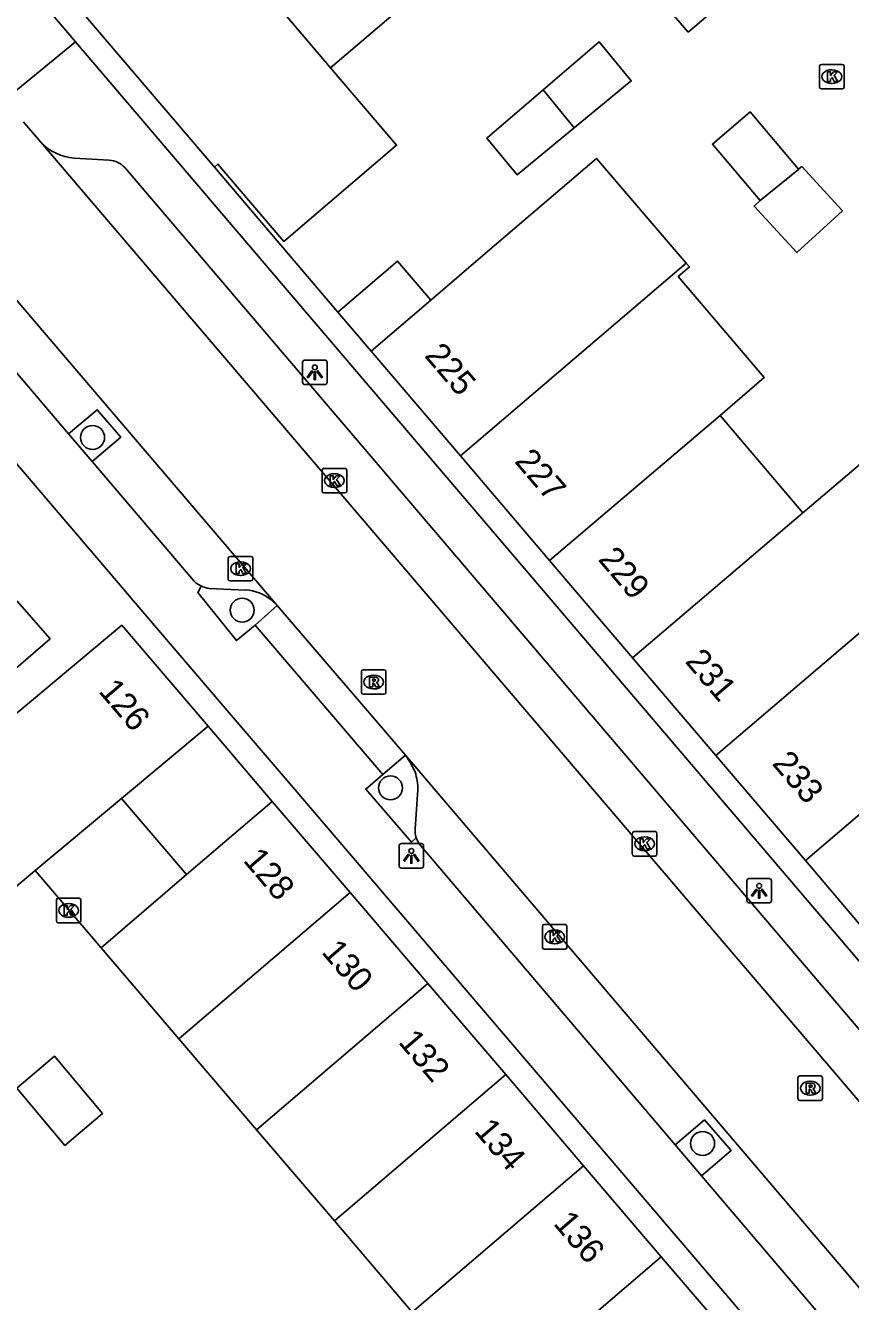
# Model space of a CAD drawing. Extents: x 160379 to 161131, y 383940 to 384849.
# Drawn here: x 160748.4 to 160782, y 384618.3 to 384670.3 of the extents above; entities that cross this region are included whole.
import ezdxf

# ---------------------------------------------------------------- set-up
doc = ezdxf.new("R2010")
doc.units = 0
for name, color, linetype in [('IMGEO_Boom', 7, 'Continuous'), ('IMGEO_Kolk', 7, 'Continuous'), ('IMGEO_Lichtpunt', 7, 'Continuous'), ('IMGEO_Muur', 7, 'Continuous'), ('IMGEO_Pand', 7, 'Continuous'), ('IMGEO_Pand_nummerreeks', 7, 'Continuous'), ('IMGEO_Pand_overbouw', 7, 'Continuous'), ('IMGEO_Parkeervlak_open', 7, 'Continuous'), ('IMGEO_Rijbaan_lokaal_open', 7, 'Continuous'), ('IMGEO_Rioolput', 7, 'Continuous'), ('IMGEO_Voetpad_open', 7, 'Continuous')]:
    doc.layers.add(name, color=color, linetype=linetype)

msp = doc.modelspace()

# ---------------------------------------------------------------- linework, layer by layer
at = {"layer": 'IMGEO_Boom'}
for centre in [(160751.133, 384653.538), (160757.232, 384646.499), (160763.277, 384639.257), (160775.998, 384624.766)]:
    msp.add_circle(centre, 0.489, dxfattribs=at)
at = {"layer": 'IMGEO_Kolk'}
for p, q in [((160780.765, 384667.817), (160780.765, 384668.669)), ((160780.84, 384668.743), (160781.692, 384668.743)), ((160781.766, 384668.669), (160781.766, 384667.817)), ((160781.253, 384668.523), (160781.278, 384668.523)), ((160781.692, 384667.743), (160780.84, 384667.743)), ((160781.276, 384667.963), (160781.251, 384667.963)), ((160760.49, 384651.353), (160760.49, 384652.205)), ((160760.565, 384652.279), (160761.417, 384652.279)), ((160760.978, 384652.059), (160761.003, 384652.059)), ((160761.491, 384652.205), (160761.491, 384651.353)), ((160761.001, 384651.499), (160760.976, 384651.499)), ((160761.417, 384651.279), (160760.565, 384651.279)), ((160756.663, 384647.764), (160756.663, 384648.616)), ((160756.738, 384648.69), (160757.59, 384648.69)), ((160757.151, 384648.47), (160757.176, 384648.47)), ((160757.664, 384648.616), (160757.664, 384647.764)), ((160757.174, 384647.91), (160757.149, 384647.91)), ((160757.59, 384647.69), (160756.738, 384647.69)), ((160773.209, 384637.478), (160774.061, 384637.478)), ((160773.134, 384636.552), (160773.134, 384637.404)), ((160773.622, 384637.258), (160773.647, 384637.258)), ((160774.135, 384637.404), (160774.135, 384636.552)), ((160774.061, 384636.478), (160773.209, 384636.478)), ((160773.645, 384636.698), (160773.62, 384636.698)), ((160749.658, 384633.837), (160749.658, 384634.689)), ((160749.733, 384634.763), (160750.585, 384634.763)), ((160750.146, 384634.543), (160750.171, 384634.543)), ((160750.659, 384634.689), (160750.659, 384633.837)), ((160750.169, 384633.983), (160750.144, 384633.983)), ((160750.585, 384633.763), (160749.733, 384633.763)), ((160769.469, 384632.758), (160769.469, 384633.61)), ((160769.544, 384633.684), (160770.396, 384633.684)), ((160769.957, 384633.464), (160769.982, 384633.464)), ((160770.47, 384633.61), (160770.47, 384632.758)), ((160769.98, 384632.904), (160769.955, 384632.904)), ((160770.396, 384632.684), (160769.544, 384632.684))]:
    msp.add_line(p, q, dxfattribs=at)
for points in [[(160780.765, 384667.817), (160780.765, 384668.669)], [(160780.84, 384668.743), (160781.692, 384668.743)], [(160781.766, 384668.669), (160781.766, 384667.817)], [(160781.086, 384668.443), (160781.209, 384668.443), (160781.209, 384668.292), (160781.339, 384668.443), (160781.503, 384668.443), (160781.357, 384668.292), (160781.51, 384668.043), (160781.358, 384668.043), (160781.273, 384668.207), (160781.209, 384668.14), (160781.209, 384668.043), (160781.086, 384668.043), (160781.086, 384668.443)], [(160781.692, 384667.743), (160780.84, 384667.743)], [(160760.49, 384651.353), (160760.49, 384652.205)], [(160760.565, 384652.279), (160761.417, 384652.279)], [(160760.811, 384651.979), (160760.934, 384651.979), (160760.934, 384651.828), (160761.064, 384651.979), (160761.228, 384651.979), (160761.082, 384651.828), (160761.235, 384651.579), (160761.083, 384651.579), (160760.998, 384651.743), (160760.934, 384651.676), (160760.934, 384651.579), (160760.811, 384651.579), (160760.811, 384651.979)], [(160761.491, 384652.205), (160761.491, 384651.353)], [(160761.417, 384651.279), (160760.565, 384651.279)], [(160756.663, 384647.764), (160756.663, 384648.616)], [(160756.738, 384648.69), (160757.59, 384648.69)], [(160756.984, 384648.39), (160757.107, 384648.39), (160757.107, 384648.239), (160757.237, 384648.39), (160757.401, 384648.39), (160757.255, 384648.239), (160757.408, 384647.99), (160757.256, 384647.99), (160757.171, 384648.154), (160757.107, 384648.087), (160757.107, 384647.99), (160756.984, 384647.99), (160756.984, 384648.39)], [(160757.664, 384648.616), (160757.664, 384647.764)], [(160757.59, 384647.69), (160756.738, 384647.69)], [(160773.209, 384637.478), (160774.061, 384637.478)], [(160773.134, 384636.552), (160773.134, 384637.404)], [(160773.455, 384637.178), (160773.578, 384637.178), (160773.578, 384637.027), (160773.708, 384637.178), (160773.872, 384637.178), (160773.726, 384637.027), (160773.879, 384636.778), (160773.727, 384636.778), (160773.642, 384636.942), (160773.578, 384636.875), (160773.578, 384636.778), (160773.455, 384636.778), (160773.455, 384637.178)], [(160774.135, 384637.404), (160774.135, 384636.552)], [(160774.061, 384636.478), (160773.209, 384636.478)], [(160749.658, 384633.837), (160749.658, 384634.689)], [(160749.733, 384634.763), (160750.585, 384634.763)], [(160749.979, 384634.463), (160750.102, 384634.463), (160750.102, 384634.312), (160750.232, 384634.463), (160750.396, 384634.463), (160750.25, 384634.312), (160750.403, 384634.063), (160750.251, 384634.063), (160750.166, 384634.227), (160750.102, 384634.16), (160750.102, 384634.063), (160749.979, 384634.063), (160749.979, 384634.463)], [(160750.659, 384634.689), (160750.659, 384633.837)], [(160750.585, 384633.763), (160749.733, 384633.763)], [(160769.469, 384632.758), (160769.469, 384633.61)], [(160769.544, 384633.684), (160770.396, 384633.684)], [(160769.79, 384633.384), (160769.913, 384633.384), (160769.913, 384633.233), (160770.043, 384633.384), (160770.207, 384633.384), (160770.061, 384633.233), (160770.214, 384632.984), (160770.062, 384632.984), (160769.977, 384633.148), (160769.913, 384633.081), (160769.913, 384632.984), (160769.79, 384632.984), (160769.79, 384633.384)], [(160770.47, 384633.61), (160770.47, 384632.758)], [(160770.396, 384632.684), (160769.544, 384632.684)]]:
    msp.add_lwpolyline(points, dxfattribs=at)
for centre, start, end in [((160780.842, 384668.667), 91.552, 178.448), ((160780.842, 384668.667), 91.552, 178.448), ((160781.69, 384668.667), 1.552, 88.448), ((160781.69, 384668.667), 1.552, 88.448), ((160780.842, 384667.819), 181.552, 268.448), ((160780.842, 384667.819), 181.552, 268.448), ((160781.69, 384667.819), 271.552, 358.448), ((160781.69, 384667.819), 271.552, 358.448), ((160760.567, 384652.203), 91.552, 178.448), ((160760.567, 384652.203), 91.552, 178.448), ((160761.415, 384652.203), 1.552, 88.448), ((160761.415, 384652.203), 1.552, 88.448), ((160760.567, 384651.355), 181.552, 268.448), ((160760.567, 384651.355), 181.552, 268.448), ((160761.415, 384651.355), 271.552, 358.448), ((160761.415, 384651.355), 271.552, 358.448), ((160756.74, 384648.614), 91.552, 178.448), ((160756.74, 384648.614), 91.552, 178.448), ((160757.588, 384648.614), 1.552, 88.448), ((160757.588, 384648.614), 1.552, 88.448), ((160756.74, 384647.766), 181.552, 268.448), ((160756.74, 384647.766), 181.552, 268.448), ((160757.588, 384647.766), 271.552, 358.448), ((160757.588, 384647.766), 271.552, 358.448), ((160773.211, 384637.402), 91.552, 178.448), ((160773.211, 384637.402), 91.552, 178.448), ((160774.059, 384637.402), 1.552, 88.448), ((160774.059, 384637.402), 1.552, 88.448), ((160773.211, 384636.554), 181.552, 268.448), ((160773.211, 384636.554), 181.552, 268.448), ((160774.059, 384636.554), 271.552, 358.448), ((160774.059, 384636.554), 271.552, 358.448), ((160749.735, 384634.687), 91.552, 178.448), ((160749.735, 384634.687), 91.552, 178.448), ((160750.583, 384634.687), 1.552, 88.448), ((160750.583, 384634.687), 1.552, 88.448), ((160749.735, 384633.839), 181.552, 268.448), ((160749.735, 384633.839), 181.552, 268.448), ((160750.583, 384633.839), 271.552, 358.448), ((160750.583, 384633.839), 271.552, 358.448), ((160769.546, 384633.608), 91.552, 178.448), ((160769.546, 384633.608), 91.552, 178.448), ((160770.394, 384633.608), 1.552, 88.448), ((160770.394, 384633.608), 1.552, 88.448), ((160769.546, 384632.76), 181.552, 268.448), ((160769.546, 384632.76), 181.552, 268.448), ((160770.394, 384632.76), 271.552, 358.448), ((160770.394, 384632.76), 271.552, 358.448)]:
    msp.add_arc(centre, 0.0765, start, end, dxfattribs=at)
for centre, major_axis, ratio, start_param, end_param in [((160781.252, 384668.243), (-0.387, 0.002), 0.722429, 4.712389, 7.853982), ((160781.277, 384668.243), (-0.39, 0.002), 0.717154, 1.570796, 4.712389), ((160760.977, 384651.779), (-0.387, 0.002), 0.722429, 4.712389, 7.853982), ((160761.002, 384651.779), (-0.39, 0.002), 0.717154, 1.570796, 4.712389), ((160757.15, 384648.19), (-0.387, 0.002), 0.722429, 4.712389, 7.853982), ((160757.175, 384648.19), (-0.39, 0.002), 0.717154, 1.570796, 4.712389), ((160773.621, 384636.978), (-0.387, 0.002), 0.722429, 4.712389, 7.853982), ((160773.646, 384636.978), (-0.39, 0.002), 0.717154, 1.570796, 4.712389), ((160750.145, 384634.263), (-0.387, 0.002), 0.722429, 4.712389, 7.853982), ((160750.17, 384634.263), (-0.39, 0.002), 0.717154, 1.570796, 4.712389), ((160769.956, 384633.184), (-0.387, 0.002), 0.722429, 4.712389, 7.853982), ((160769.981, 384633.184), (-0.39, 0.002), 0.717154, 1.570796, 4.712389)]:
    msp.add_ellipse(centre, major_axis=major_axis, ratio=ratio, start_param=start_param, end_param=end_param, dxfattribs=at)
at = {"layer": 'IMGEO_Lichtpunt'}
for p, q in [((160760.595, 384656.691), (160759.787, 384656.691)), ((160760.595, 384656.691), (160759.787, 384656.691)), ((160759.693, 384656.596), (160759.693, 384655.789)), ((160759.693, 384656.596), (160759.693, 384655.789)), ((160760.689, 384655.789), (160760.689, 384656.596)), ((160760.689, 384655.789), (160760.689, 384656.596)), ((160759.787, 384655.695), (160760.595, 384655.695)), ((160759.787, 384655.695), (160760.595, 384655.695)), ((160763.627, 384636.89), (160763.627, 384636.083)), ((160763.627, 384636.89), (160763.627, 384636.083)), ((160764.529, 384636.985), (160763.721, 384636.985)), ((160764.529, 384636.985), (160763.721, 384636.985)), ((160764.623, 384636.083), (160764.623, 384636.89)), ((160764.623, 384636.083), (160764.623, 384636.89)), ((160763.721, 384635.989), (160764.529, 384635.989)), ((160763.721, 384635.989), (160764.529, 384635.989)), ((160777.805, 384635.467), (160777.805, 384634.66)), ((160777.805, 384635.467), (160777.805, 384634.66)), ((160778.707, 384635.562), (160777.899, 384635.562)), ((160778.707, 384635.562), (160777.899, 384635.562)), ((160778.801, 384634.66), (160778.801, 384635.467)), ((160778.801, 384634.66), (160778.801, 384635.467)), ((160777.899, 384634.566), (160778.707, 384634.566)), ((160777.899, 384634.566), (160778.707, 384634.566))]:
    msp.add_line(p, q, dxfattribs=at)
for points in [[(160760.067, 384656.26), (160760.106, 384656.232), (160759.918, 384655.97), (160759.88, 384655.997), (160760.067, 384656.26)], [(160760.169, 384656.212), (160760.216, 384656.212), (160760.216, 384655.89), (160760.169, 384655.89), (160760.169, 384656.212)], [(160760.279, 384656.232), (160760.317, 384656.259), (160760.504, 384655.997), (160760.465, 384655.969), (160760.279, 384656.232)], [(160764.001, 384636.554), (160764.04, 384636.526), (160763.852, 384636.264), (160763.814, 384636.291), (160764.001, 384636.554)], [(160764.103, 384636.506), (160764.15, 384636.506), (160764.15, 384636.184), (160764.103, 384636.184), (160764.103, 384636.506)], [(160764.213, 384636.526), (160764.251, 384636.553), (160764.438, 384636.291), (160764.399, 384636.263), (160764.213, 384636.526)], [(160778.179, 384635.131), (160778.218, 384635.103), (160778.03, 384634.841), (160777.992, 384634.868), (160778.179, 384635.131)], [(160778.281, 384635.083), (160778.328, 384635.083), (160778.328, 384634.761), (160778.281, 384634.761), (160778.281, 384635.083)], [(160778.391, 384635.103), (160778.429, 384635.13), (160778.616, 384634.868), (160778.577, 384634.84), (160778.391, 384635.103)]]:
    msp.add_lwpolyline(points, dxfattribs=at)
for centre in [(160760.192, 384656.394), (160764.126, 384636.688), (160778.304, 384635.265)]:
    msp.add_circle(centre, 0.0994, dxfattribs=at)
for centre, start, end in [((160759.787, 384656.596), 90, 180), ((160759.787, 384656.596), 90, 180), ((160760.595, 384656.596), 0, 90), ((160760.595, 384656.596), 0, 90), ((160759.787, 384655.789), 180, 270), ((160759.787, 384655.789), 180, 270), ((160760.595, 384655.789), 270, 0), ((160760.595, 384655.789), 270, 360), ((160763.721, 384636.89), 90, 180), ((160763.721, 384636.89), 90, 180), ((160764.529, 384636.89), 0, 90), ((160764.529, 384636.89), 0, 90), ((160763.721, 384636.083), 180, 270), ((160763.721, 384636.083), 180, 270), ((160764.529, 384636.083), 270, 0), ((160764.529, 384636.083), 270, 360), ((160777.899, 384635.467), 90, 180), ((160777.899, 384635.467), 90, 180), ((160778.707, 384635.467), 0, 90), ((160778.707, 384635.467), 0, 90), ((160777.899, 384634.66), 180, 270), ((160777.899, 384634.66), 180, 270), ((160778.707, 384634.66), 270, 0), ((160778.707, 384634.66), 270, 360)]:
    msp.add_arc(centre, 0.0946, start, end, dxfattribs=at)
at = {"layer": 'IMGEO_Muur'}
msp.add_lwpolyline([(160756.097, 384664.552), (160761.133, 384658.642)], dxfattribs=at)
at = {"layer": 'IMGEO_Pand'}
for points in [[(160756.097, 384664.552), (160749.668, 384672.104), (160750.064, 384672.428), (160750.276, 384672.18), (160754.422, 384675.731), (160754.212, 384675.976), (160754.419, 384676.148)], [(160754.419, 384676.148), (160760.831, 384668.595)], [(160775.407, 384670.052), (160774.083, 384671.616), (160776.366, 384673.561), (160777.685, 384672.002), (160775.407, 384670.052)], [(160765.402, 384672.498), (160760.831, 384668.595)], [(160769.497, 384667.698), (160771.787, 384669.655), (160773.09, 384668.071), (160770.764, 384666.157)], [(160760.831, 384668.595), (160763.523, 384665.443), (160758.935, 384661.524), (160756.243, 384664.677), (160756.097, 384664.552)], [(160770.764, 384666.157), (160768.438, 384664.244), (160767.206, 384665.741), (160769.497, 384667.698)], [(160769.497, 384667.698), (160770.764, 384666.157)], [(160779.907, 384664.465), (160777.932, 384666.802), (160776.397, 384665.491), (160778.339, 384663.188)], [(160764.917, 384659.139), (160767.231, 384661.115), (160771.671, 384664.908), (160775.332, 384660.634)], [(160778.339, 384663.188), (160778.094, 384662.962), (160779.842, 384661.069), (160781.695, 384662.779), (160780.037, 384664.575), (160779.907, 384664.465)], [(160779.907, 384664.465), (160779.909, 384664.462), (160778.339, 384663.188)], [(160761.133, 384658.642), (160763.566, 384660.72), (160764.917, 384659.139)], [(160766.124, 384652.79), (160775.332, 384660.634)], [(160775.332, 384660.634), (160775.459, 384660.486), (160775.009, 384660.097), (160778.51, 384655.985), (160776.709, 384654.436)], [(160764.917, 384659.139), (160762.484, 384657.06)], [(160761.133, 384658.642), (160762.484, 384657.06)], [(160762.484, 384657.06), (160766.124, 384652.79)], [(160769.763, 384648.52), (160776.709, 384654.436)], [(160776.709, 384654.436), (160780.085, 384650.46)], [(160766.124, 384652.79), (160769.763, 384648.52)], [(160780.085, 384650.46), (160782.712, 384652.698), (160786.09, 384648.71), (160785.294, 384648.036)], [(160773.147, 384644.55), (160780.085, 384650.46)], [(160769.763, 384648.52), (160773.147, 384644.55)], [(160785.294, 384648.036), (160783.461, 384646.484), (160776.531, 384640.581)], [(160745.78, 384644.919), (160748.058, 384646.872), (160749.401, 384645.333), (160747.109, 384643.368)], [(160755.839, 384641.77), (160752.323, 384645.885), (160744.359, 384639.228), (160742.15, 384637.381), (160745.62, 384633.23), (160747.828, 384635.077), (160748.794, 384635.885), (160752.317, 384638.828), (160755.839, 384641.77)], [(160776.531, 384640.581), (160773.147, 384644.55)], [(160788.961, 384643.766), (160780.186, 384636.292)], [(160776.531, 384640.581), (160780.186, 384636.292)], [(160754.648, 384629.033), (160751.476, 384632.745), (160754.966, 384635.727), (160758.456, 384638.708), (160761.628, 384634.996)], [(160780.186, 384636.292), (160783.756, 384632.103)], [(160761.628, 384634.996), (160754.648, 384629.033)], [(160761.628, 384634.996), (160764.8, 384631.283)], [(160764.8, 384631.283), (160757.82, 384625.32)], [(160764.8, 384631.283), (160767.972, 384627.571)], [(160757.82, 384625.32), (160754.648, 384629.033)], [(160749.997, 384624.688), (160748.043, 384627.014), (160749.582, 384628.317), (160751.538, 384625.992), (160749.997, 384624.688)], [(160767.972, 384627.571), (160760.992, 384621.608)], [(160767.972, 384627.571), (160771.144, 384623.858)], [(160760.992, 384621.608), (160757.82, 384625.32)], [(160771.144, 384623.858), (160764.164, 384617.895)], [(160771.144, 384623.858), (160774.316, 384620.146)], [(160764.164, 384617.895), (160760.992, 384621.608)], [(160774.316, 384620.146), (160767.337, 384614.183)], [(160774.316, 384620.146), (160777.488, 384616.433)]]:
    msp.add_lwpolyline(points, dxfattribs=at)
at = {"layer": 'IMGEO_Pand_overbouw'}
for points in [[(160752.317, 384638.828), (160754.966, 384635.727), (160758.456, 384638.708), (160755.839, 384641.77)], [(160752.317, 384638.828), (160748.794, 384635.885), (160751.476, 384632.745), (160754.966, 384635.727)]]:
    msp.add_lwpolyline(points, close=True, dxfattribs=at)
at = {"layer": 'IMGEO_Parkeervlak_open'}
for points in [[(160751.116, 384652.558), (160752.28, 384653.556), (160751.324, 384654.668), (160750.157, 384653.683)], [(160757.368, 384647.321), (160755.885, 384647.387)], [(160758.652, 384646.689), (160758.41, 384646.923)], [(160763.891, 384640.584), (160764.067, 384640.322), (160764.277, 384639.906)], [(160764.388, 384639.174), (160764.284, 384637.589)], [(160775.954, 384623.453), (160777.163, 384624.482), (160776.07, 384625.726), (160774.881, 384624.714)]]:
    msp.add_lwpolyline(points, dxfattribs=at)
for centre, radius, start, end in [((160756.054, 384648.545), 1.17, 245.0492, 261.7141), ((160757.27, 384645.501), 1.823, 51.2782, 86.9123), ((160762.289, 384639.23), 2.1, 358.4704, 18.7748), ((160765.207, 384637.513), 0.926, 175.2658, 197.9701)]:
    msp.add_arc(centre, radius, start, end, dxfattribs=at)
at = {"layer": 'IMGEO_Rijbaan_lokaal_open'}
for points in [[(160748.316, 384666.394), (160748.341, 384666.363), (160749.03, 384665.578)], [(160795.82, 384610.729), (160749.03, 384665.578)], [(160745.67, 384661.89), (160758.652, 384646.689)], [(160758.652, 384646.689), (160763.891, 384640.584)], [(160792.118, 384607.459), (160763.891, 384640.584)]]:
    msp.add_lwpolyline(points, dxfattribs=at)
at = {"layer": 'IMGEO_Rioolput'}
for p, q in [((160762.09, 384643.144), (160762.09, 384643.996)), ((160762.165, 384644.07), (160763.017, 384644.07)), ((160762.578, 384643.85), (160762.603, 384643.85)), ((160763.091, 384643.996), (160763.091, 384643.144)), ((160762.601, 384643.29), (160762.576, 384643.29)), ((160763.017, 384643.07), (160762.165, 384643.07)), ((160779.886, 384626.592), (160779.886, 384627.444)), ((160779.961, 384627.518), (160780.813, 384627.518)), ((160780.374, 384627.298), (160780.399, 384627.298)), ((160780.887, 384627.444), (160780.887, 384626.592)), ((160780.813, 384626.518), (160779.961, 384626.518)), ((160780.397, 384626.738), (160780.372, 384626.738))]:
    msp.add_line(p, q, dxfattribs=at)
for points in [[(160762.09, 384643.144), (160762.09, 384643.996)], [(160762.165, 384644.07), (160763.017, 384644.07)], [(160762.679, 384643.768), (160762.427, 384643.77), (160762.427, 384643.37)], [(160762.605, 384643.689), (160762.551, 384643.689), (160762.551, 384643.608)], [(160763.091, 384643.996), (160763.091, 384643.144)], [(160762.427, 384643.37), (160762.551, 384643.37), (160762.551, 384643.532), (160762.562, 384643.532)], [(160762.551, 384643.608), (160762.603, 384643.608)], [(160762.609, 384643.503), (160762.68, 384643.37), (160762.82, 384643.37), (160762.755, 384643.496)], [(160763.017, 384643.07), (160762.165, 384643.07)], [(160779.886, 384626.592), (160779.886, 384627.444)], [(160779.961, 384627.518), (160780.813, 384627.518)], [(160780.475, 384627.216), (160780.223, 384627.218), (160780.223, 384626.818)], [(160780.401, 384627.137), (160780.347, 384627.137), (160780.347, 384627.056)], [(160780.347, 384627.056), (160780.399, 384627.056)], [(160780.887, 384627.444), (160780.887, 384626.592)], [(160780.813, 384626.518), (160779.961, 384626.518)], [(160780.223, 384626.818), (160780.347, 384626.818), (160780.347, 384626.98), (160780.358, 384626.98)], [(160780.405, 384626.951), (160780.476, 384626.818), (160780.616, 384626.818), (160780.551, 384626.944)]]:
    msp.add_lwpolyline(points, dxfattribs=at)
for centre, radius, start, end in [((160762.167, 384643.994), 0.0765, 91.552, 178.448), ((160762.167, 384643.994), 0.0765, 91.552, 178.448), ((160762.611, 384643.593), 0.0964, 77.0061, 93.1865), ((160762.625, 384643.65), 0.0378, 276.6634, 79.6772), ((160762.678, 384643.658), 0.109, 350.3612, 89.416), ((160763.015, 384643.994), 0.0765, 1.552, 88.448), ((160763.015, 384643.994), 0.0765, 1.552, 88.448), ((160762.167, 384643.146), 0.0765, 181.552, 268.448), ((160762.167, 384643.146), 0.0765, 181.552, 268.448), ((160762.561, 384643.479), 0.0533, 26.0293, 88.6989), ((160762.587, 384643.797), 0.19, 274.7715, 282.9687), ((160762.676, 384643.658), 0.112, 277.5842, 350.9817), ((160762.66, 384643.443), 0.108, 29.5134, 73.7905), ((160763.015, 384643.146), 0.0765, 271.552, 358.448), ((160763.015, 384643.146), 0.0765, 271.552, 358.448), ((160779.963, 384627.442), 0.0765, 91.552, 178.448), ((160779.963, 384627.442), 0.0765, 91.552, 178.448), ((160780.383, 384627.245), 0.19, 274.7715, 282.9687), ((160780.407, 384627.041), 0.0964, 77.0061, 93.1865), ((160780.421, 384627.098), 0.0378, 276.6634, 79.6772), ((160780.474, 384627.106), 0.109, 350.3612, 89.416), ((160780.472, 384627.106), 0.112, 277.5842, 350.9817), ((160780.811, 384627.442), 0.0765, 1.552, 88.448), ((160780.811, 384627.442), 0.0765, 1.552, 88.448), ((160779.963, 384626.594), 0.0765, 181.552, 268.448), ((160779.963, 384626.594), 0.0765, 181.552, 268.448), ((160780.357, 384626.927), 0.0533, 26.0293, 88.6989), ((160780.456, 384626.891), 0.108, 29.5134, 73.7905), ((160780.811, 384626.594), 0.0765, 271.552, 358.448), ((160780.811, 384626.594), 0.0765, 271.552, 358.448)]:
    msp.add_arc(centre, radius, start, end, dxfattribs=at)
for centre, major_axis, ratio, start_param, end_param in [((160762.577, 384643.57), (-0.387, 0.002), 0.722429, 4.712389, 7.853982), ((160762.602, 384643.57), (-0.39, 0.002), 0.717154, 1.570796, 4.712389), ((160780.373, 384627.018), (-0.387, 0.002), 0.722429, 4.712389, 7.853982), ((160780.398, 384627.018), (-0.39, 0.002), 0.717154, 1.570796, 4.712389)]:
    msp.add_ellipse(centre, major_axis=major_axis, ratio=ratio, start_param=start_param, end_param=end_param, dxfattribs=at)
at = {"layer": 'IMGEO_Voetpad_open'}
for points in [[(160750.44, 384669.667), (160748.889, 384671.488), (160748.482, 384671.944), (160767.838, 384688.52), (160768.3, 384687.993)], [(160750.44, 384669.667), (160747.56, 384667.294)], [(160824.919, 384548.707), (160818.812, 384581.761), (160816.984, 384591.607), (160750.44, 384669.667)], [(160750.386, 384664.926), (160751.813, 384664.834)], [(160752.443, 384664.534), (160812.448, 384594.132)], [(160756.097, 384664.552), (160761.133, 384658.642)], [(160814.707, 384533.039), (160805.221, 384581.626), (160804.227, 384586.696), (160801.827, 384589.484), (160785.555, 384608.533), (160784.593, 384609.659), (160759.221, 384639.361), (160756.612, 384642.415), (160753.096, 384646.531), (160752.089, 384647.71), (160738.611, 384663.488)], [(160750.157, 384653.683), (160746.136, 384658.404)], [(160750.157, 384653.683), (160751.116, 384652.558)], [(160755.258, 384647.695), (160751.116, 384652.558)], [(160757.758, 384645.893), (160756.995, 384645.261), (160755.421, 384647.213), (160755.56, 384647.484)], [(160758.652, 384646.689), (160757.758, 384645.893)], [(160762.96, 384639.806), (160757.758, 384645.893)], [(160762.96, 384639.806), (160763.891, 384640.584)], [(160764.326, 384637.227), (160764.127, 384637.039), (160762.265, 384639.208), (160762.96, 384639.806)], [(160764.518, 384636.892), (160774.881, 384624.714)], [(160774.881, 384624.714), (160775.954, 384623.453)], [(160775.954, 384623.453), (160790.977, 384605.8)]]:
    msp.add_lwpolyline(points, dxfattribs=at)
for centre, radius, start, end in [((160750.502, 384666.904), 1.982, 222.0092, 266.6319), ((160751.77, 384663.931), 0.904, 41.8271, 87.2462), ((160756.035, 384648.486), 1.109, 225.5001, 244.6178), ((160765.189, 384637.499), 0.905, 197.4977, 222.1393)]:
    msp.add_arc(centre, radius, start, end, dxfattribs=at)

# ---------------------------------------------------------------- texts
at = {"layer": 'IMGEO_Pand_nummerreeks'}
for s, rotation, p in [('225', 310.4435, (160764.628, 384656.857)), ('227', 310.4435, (160768.299, 384652.55)), ('229', 310.4435, (160771.706, 384648.554)), ('231', 310.4449, (160775.25, 384644.396)), ('126', 310.5136, (160751.345, 384643.181)), ('233', 310.4435, (160778.797, 384640.234)), ('128', 310.5136, (160757.236, 384636.287)), ('130', 310.5136, (160760.431, 384632.549)), ('132', 310.5136, (160763.56, 384628.886)), ('134', 310.5136, (160766.656, 384625.262)), ('136', 310.5136, (160769.878, 384621.491))]:
    msp.add_text(s, height=1, rotation=rotation, dxfattribs=at).set_placement(p)

doc.saveas('drawing.dxf')
